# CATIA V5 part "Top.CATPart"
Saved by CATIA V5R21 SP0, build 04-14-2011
Part number: Top
Bounding box of the stored display mesh (mm): x -92.8 to 92.8, y 0 to 102.089, z 0 to 2.8
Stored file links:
  C:\Users\Pouria\Desktop\Box\Top.CATPart
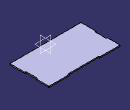
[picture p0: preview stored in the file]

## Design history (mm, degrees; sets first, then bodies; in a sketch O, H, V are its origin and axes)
Body1 (main body)
  Sketch1 on xy-plane, origin (0, 0, 0), H (1, 0, 0), V (0, 1, 0)
    point P1 (-92.8, 0)
    line L1 (-92.8, 0) -> (92.8, 0)
    line L2 (92.8, 0) -> (92.8, 39.289)
    line L3 (92.8, 102.089) -> (40, 102.089)
    line L4 (-92.8, 102.089) -> (-92.8, 69.289)
    point P2 (92.8, 0)
    point P3 (92.8, 102.089)
    point P5 (92.8, 69.289)
    line L5 (92.8, 69.289) -> (90, 69.289)
    line L6 (90, 69.289) -> (90, 39.289)
    line L7 (90, 39.289) -> (92.8, 39.289)
    line L8 (-92.8, 69.289) -> (-90, 69.289)
    line L9 (-90, 69.289) -> (-90, 39.289)
    line L10 (-90, 39.289) -> (-92.8, 39.289)
    point P12 (-92.8, 39.289)
    point P13 (-40, 102.089)
    line L11 (-40, 102.089) -> (-40, 99.289)
    line L12 (-40, 99.289) -> (40, 99.289)
    line L13 (40, 99.289) -> (40, 102.089)
    line L14 (92.8, 69.289) -> (92.8, 102.089)
    line L15 (-40, 102.089) -> (-92.8, 102.089)
    line L16 (-92.8, 39.289) -> (-92.8, 0)
    length L1 = 185.6
    distance L6 L2 = 2.8
    distance L9 L4 = 2.8
    distance L5 L3 = 32.8
    distance L8 L3 = 32.8
    length L6 = 30
    length L9 = 30
    length L12 = 80
    length L13 = 2.8
    distance P2 P3 = 102.089
    coincidence: P1 H, P5 L2, P12 L4, P13 L3, L2 L14, L3 L15, L4 L16
    horizontal: L1 H, L3 H, L5 H, L7 H, L8 H, L10 H, L12 H, L15 H
    vertical: L2 V, L4 V, L6 V, L9 V, L11 V, L13 V, L14 V, L16 V
    symmetry: L2 L4 V, L13 L11 V
  Pad1: profile Sketch1, direction (0, 0, 1), length 2.8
